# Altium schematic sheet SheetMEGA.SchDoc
size A4
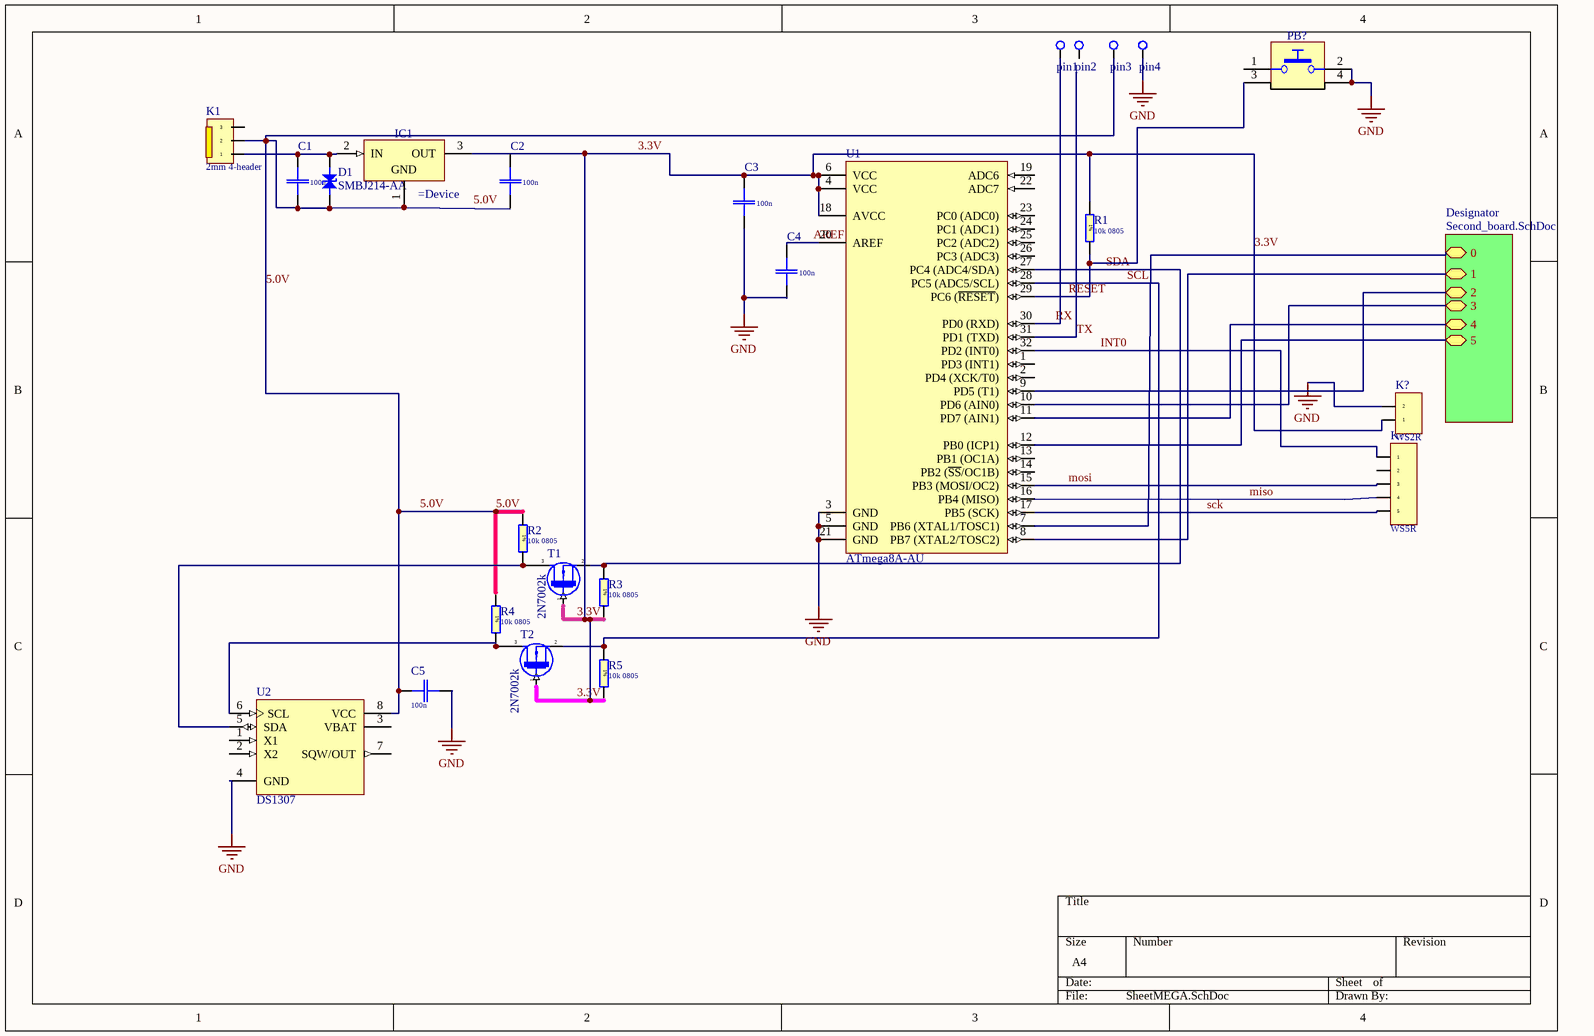
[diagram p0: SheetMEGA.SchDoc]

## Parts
(Parts that share a designator on the sheet are numbered #1, #2 ... from top to bottom, then left to right.)
C1  100n  [C1206(3216)]
C2  100n  [C1206(3216)]
C3  100n  [C1206(3216)]
C4  100n  [C1206(3216)]
C5  100n  [C1206(3216)]
D1  SMBJ214-AA  [DO-214AA (SMB)]
IC1  (no value)  [SOT89]
K1  2mm 4-header  [SherKhan Con _3_PIN]
K?#1  WS2R  [WS2R]
K?#2  WS5R  [WS5R]
PB?  Push Button  [PB_ALPS_SKHHLMA010]  (value not drawn)
pin1  H-1  [J1]  (value not drawn)
pin2  H-1  [J1]  (value not drawn)
pin3  H-1  [J1]  (value not drawn)
pin4  H-1  [J1]  (value not drawn)
R1  10k 0805  [0805]
R2  10k 0805  [0805]
R3  10k 0805  [0805]
R4  10k 0805  [0805]
R5  10k 0805  [0805]
T1  2N7002k  [SOT23]
T2  2N7002k  [SOT23]
U1  ATmega8A-AU  [32A_N]
U2  DS1307  [DIP8]

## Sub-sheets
Designator = Second_board.SchDoc: 0, 1, 2, 3, 4, 5

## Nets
GND: C3.2 C4.2 C5.2 K?#1.2 PB?.2 PB?.4 pin4.1 U1.3(GND) U1.5(GND) U1.21(GND) U2.4(GND)
3.3V: C3.1 IC1.3(OUT) K?#1.1 R1.2 R3.2 R5.2 T1.1(G) T2.1(G) U1.4(VCC) U1.6(VCC) U1.18(AVCC)
5.0V: C1.2 C5.1 D1.2(C) IC1.1(GND) K1.2 pin3.1 R2.1 R4.1 U2.8(VCC)
AREF: C4.1 U1.20(AREF)
INT0: K?#2.1 U1.32(PD2_(INT0))
miso: K?#2.4 U1.16(PB4_(MISO))
mosi: K?#2.3 U1.15(PB3_(MOSI/OC2))
RESET: PB?.3 R1.2 U1.29(PC6_(~{RESET}))
RX: pin1.1 U1.30(PD0_(RXD))
sck: K?#2.5 U1.17(PB5_(SCK))
SCL: R5.1 T2.2(S) U1.28(PC5_(ADC5/SCL))
SDA: R3.1 T1.2(S) U1.27(PC4_(ADC4/SDA))
TX: U1.31(PD1_(TXD))
NetC1_1: C1.1 D1.1(A) IC1.2(IN) K1.1
NetR2_2: R2.2 T1.3(D) U2.5(SDA)
NetR4_2: R4.2 T2.3(D) U2.6(SCL)
NetU1_7: U1.7(PB6_(XTAL1/TOSC1)) ; sheet Designator/0
NetU1_8: U1.8(PB7_(XTAL2/TOSC2)) ; sheet Designator/1
NetU1_9: U1.9(PD5_(T1)) ; sheet Designator/2
NetU1_10: U1.10(PD6_(AIN0)) ; sheet Designator/3
NetU1_11: U1.11(PD7_(AIN1)) ; sheet Designator/4
NetU1_12: U1.12(PB0_(ICP1)) ; sheet Designator/5

Not connected (* = marked no-connect by the designer): C2 1 2; K1 3; K?#2 2; PB? 1; pin2 1; U1 1(PD3_(INT1)) 2(PD4_(XCK/T0)) 13(PB1_(OC1A)) 14(PB2_(~{SS}/OC1B)) 19(ADC6) 22(ADC7) 23(PC0_(ADC0)) 24(PC1_(ADC1)) 25(PC2_(ADC2)) 26(PC3_(ADC3)); U2 1(X1) 2(X2) 3(VBAT) 7(SQW/OUT)

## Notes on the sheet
- Labels drawn without touching a wire or pin: 5.0V

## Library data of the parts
C1-C5 = C_1206: SMD-0805 50V Y5V +80/-20%
D1 = SMBJ214-AA: Диод защитный двунаправленный. пробивается на 6.1
IC1 = MCP1703T-3302e/mb: 3.3VDO; напряжение: 3.3V VDO; Ток макс.: 250mA; Ножки: 1GND-2IN-3OUT
K1 = SherKhan con_3_PIN: 2mm_step
K?#1 = WS2R: 2.5mm 3A/250V
K?#2 = WS5R: 2.5mm 3A/250V
PB? = PB_ALPS_SKHHLMA010: Push-Button Switch SPDT; Part Description: 6x6mm, SPST Horizontal Pushbutton Switch, Stem height 3.85mm, Contact Rating 50mA 12VDC, Serie SKHH; Manufacturer: ALPS; Table: Switches
R1-R5 = R-0805-1%: SMD 0805 0.1W 1% 150V
T1 T2 = 2N7002k: N-MOS 60V 7.5om 0.115mA
U1 = ATmega8A-AU: 8-bit AVR Microcontroller, 8KB Flash, 512 Bytes EEPROM, 1KB SRAM, 32-pin TQFP, Industrial Grade (-40°C to 85°C)
U2 = DS1307: 64 X 8 Serial Real-Time Clock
